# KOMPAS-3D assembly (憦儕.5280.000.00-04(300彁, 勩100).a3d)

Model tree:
1. Плоскость XY
2. Плоскость ZX
3. Плоскость ZY
4. Ось X
5. Ось Y
6. Ось Z
7. Начало координат  (labels: Операция без истории:1; ␣1␣1; ́3␣č; ␣3␣ĳ)

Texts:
  Линия-выноска #1
  Линия-выноска #2
  Линия-выноска #3
  Отклонения формы и база
  Марка координационной оси
  Марка/позиционное обозначение с линией-выноской
  Марка/позиционное обозначение на линии
  Марка/позиционное обозначение без линии-выноски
